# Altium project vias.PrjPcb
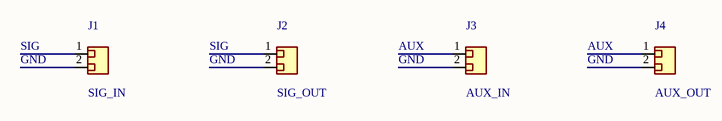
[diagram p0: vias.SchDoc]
1 sheet, 4 parts. Net scope: global (net labels, ports and power ports of the same name join across sheets).
Board file: vias.PcbDoc

## Sheet vias.SchDoc
size A4

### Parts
J1  SIG_IN  [Header_1x2_P2.54]
J2  SIG_OUT  [Header_1x2_P2.54]
J3  AUX_IN  [Header_1x2_P2.54]
J4  AUX_OUT  [Header_1x2_P2.54]

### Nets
AUX: J3.1(Passive) J4.1(Passive)
GND: J1.2(Passive) J2.2(Passive) J3.2(Passive) J4.2(Passive)
SIG: J1.1(Passive) J2.1(Passive)

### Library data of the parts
J1-J4 = Connector_2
